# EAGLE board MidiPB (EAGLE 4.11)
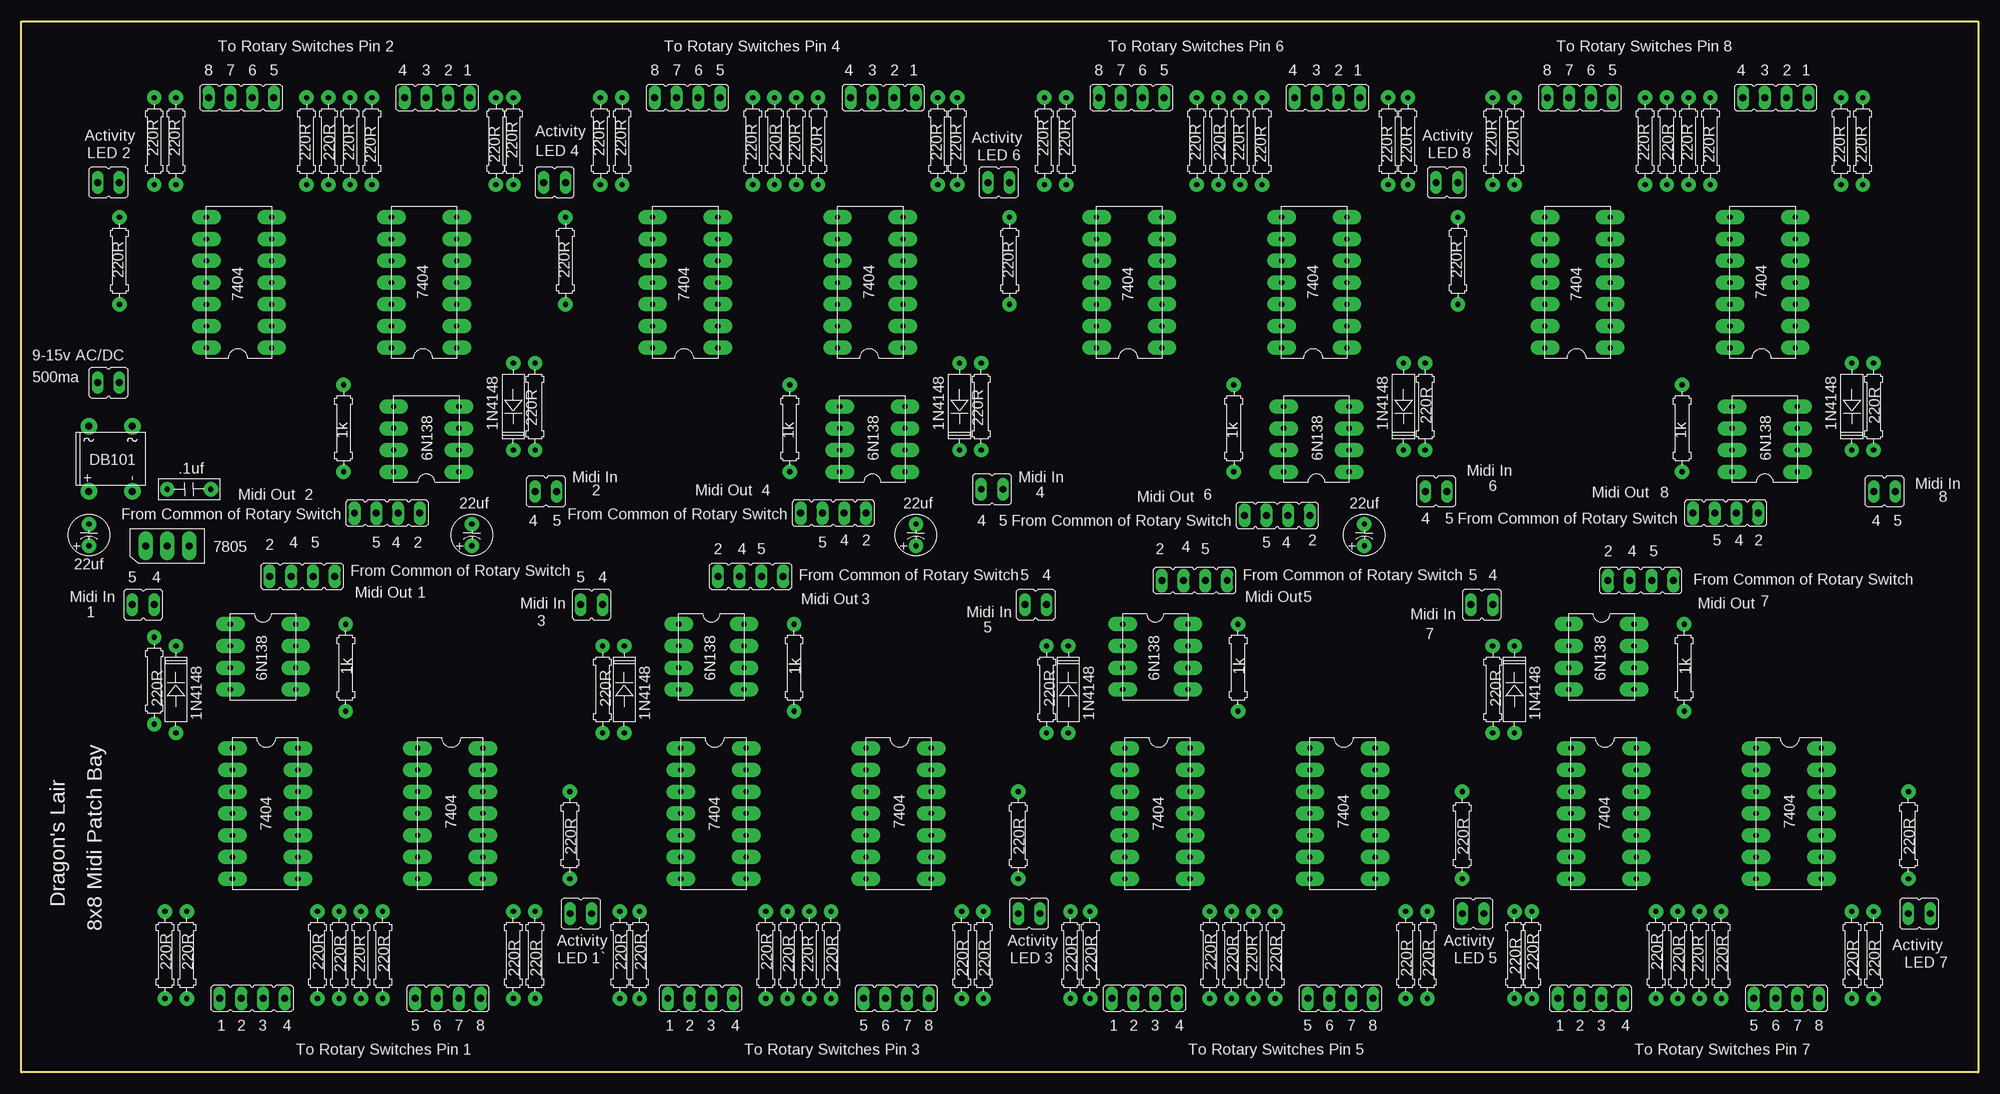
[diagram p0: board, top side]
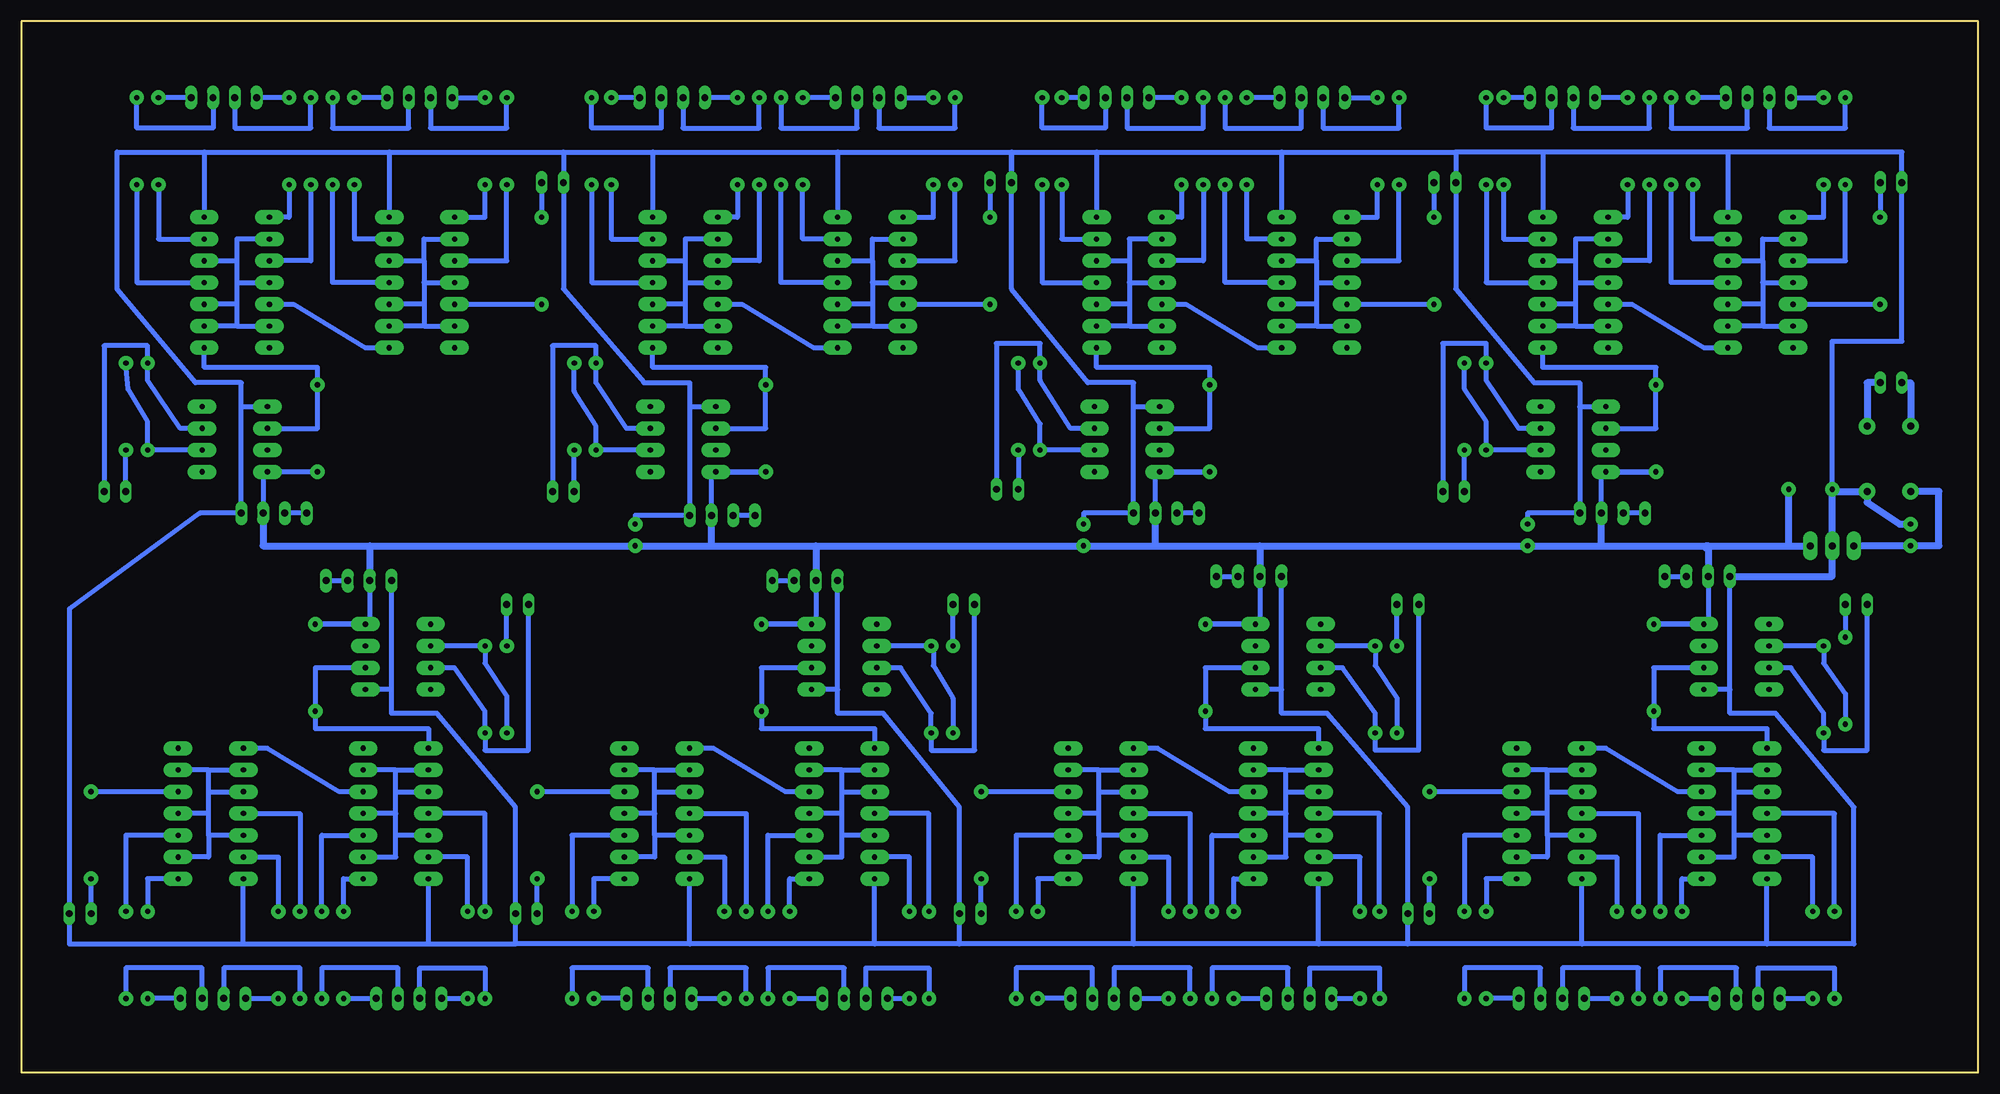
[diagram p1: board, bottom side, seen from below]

Size 228.35 x 122.68 mm. Coordinates in mm from the lower left corner, seen from the top.
Outline: 228.35,122.68 228.35,0 0,0 0,122.68 228.35,122.68
Copper layers (1*16): Top 0.035mm / dielectric 1.5mm / Bottom 0.035mm
Design rules "default": minimum track width 10mil, minimum drill 24mil, track to track 8mil, track to pad 8mil, pad to pad 8mil, via to via 8mil, smd to smd 8mil, copper to edge 40mil, drill to drill 8mil, minimum pad ring 10mil, minimum via ring 8mil, stop-mask expansion 4mil, vias tented up to drill 0mil, thermal gap 10mil

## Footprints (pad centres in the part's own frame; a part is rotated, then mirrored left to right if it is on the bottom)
DIP-8 = drill 0.61 pad 1.676 long: P$1 -3.81,3.81; P$2 -3.81,1.27; P$3 -3.81,-1.27; P$4 -3.81,-3.81; P$5 3.81,-3.81; P$6 3.81,-1.27; P$7 3.81,1.27; P$8 3.81,3.81
DIP-14 = drill 0.61 pad 1.676 long: P$1 -3.81,0; P$2 3.81,0; P$3 3.81,2.54; P$4 -3.81,2.54; P$5 -3.81,5.08; P$6 3.81,5.08; P$7 3.81,-2.54; P$8 -3.81,-2.54; P$9 -3.81,-5.08; P$10 3.81,-5.08; P$11 3.81,7.62; P$12 -3.81,7.62; P$13 -3.81,-7.62; P$14 3.81,-7.62
DIODE-1AMP = drill 0.61 pad 1.676 round: P$1 -5.08,0; P$2 5.08,0
RESISTOR = drill 0.61 pad 1.676 round: P$1 -5.08,0; P$2 5.08,0
HEADER-2 = drill 0.813 long: P$1 -1.27,0; P$2 1.27,0
HEADER-4 = drill 0.813 pad 1.422 long: P$1 -3.81,0; P$2 -1.27,0; P$3 1.27,0; P$4 3.81,0
ELECTROLYTIC1/1 = drill 0.61 pad 1.676 round: P$1 1.27,0; P$2 -1.27,0
CERAMIC1/2 = drill 0.61 pad 1.676 round: P$1 -2.54,0; P$2 2.54,0
TO-220 = drill 0.813 pad 1.676 long: P$1 -1.27,0; P$2 1.27,0; P$3 -3.81,0
DB101 = drill 0.813 pad 1.93 round: P$1 -3.81,-2.54; P$2 -3.81,2.54; P$3 3.81,2.54; P$4 3.81,-2.54

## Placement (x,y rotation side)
E$1  [DIP-8]  28.19,48.51 0 top
E$2  [DIP-14]  28.45,30.23 0 top
E$3  [DIP-14]  50.04,30.23 0 top
E$4  [DIODE-1AMP]  18.03,44.7 270 top
E$5  [RESISTOR]  37.85,47.24 90 top
E$6  [RESISTOR]  15.49,45.72 270 top
E$7  [RESISTOR]  16.76,13.72 90 top
E$8  [RESISTOR]  19.3,13.72 90 top
E$9  [RESISTOR]  34.54,13.72 90 top
E$10  [RESISTOR]  37.08,13.72 90 top
E$11  [RESISTOR]  39.62,13.72 90 top
E$12  [RESISTOR]  42.16,13.72 90 top
E$13  [RESISTOR]  59.94,13.72 90 top
E$14  [RESISTOR]  57.4,13.72 90 top
E$15  [RESISTOR]  64.01,27.69 90 top
E$16  [HEADER-2]  14.22,54.61 0 top
E$17  [HEADER-2]  65.28,18.54 0 top
E$18  [HEADER-4]  26.92,8.64 0 top
E$19  [HEADER-4]  49.78,8.64 0 top
E$20  [DIP-8]  80.52,48.51 0 top
E$21  [HEADER-4]  32.77,57.91 0 top
E$22  [DIP-14]  80.77,30.23 0 top
E$23  [DIP-14]  102.36,30.23 0 top
E$24  [DIODE-1AMP]  70.36,44.7 270 top
E$25  [RESISTOR]  90.17,47.24 90 top
E$26  [RESISTOR]  67.82,44.7 270 top
E$27  [RESISTOR]  69.85,13.72 90 top
E$28  [RESISTOR]  72.14,13.72 90 top
E$29  [RESISTOR]  86.87,13.72 90 top
E$30  [RESISTOR]  89.41,13.72 90 top
E$31  [RESISTOR]  91.95,13.72 90 top
E$32  [RESISTOR]  94.49,13.72 90 top
E$33  [RESISTOR]  112.27,13.72 90 top
E$34  [RESISTOR]  109.73,13.72 90 top
E$35  [RESISTOR]  116.33,27.69 90 top
E$36  [HEADER-2]  66.55,54.61 0 top
E$37  [HEADER-2]  117.6,18.54 0 top
E$38  [HEADER-4]  79.25,8.64 0 top
E$39  [HEADER-4]  102.11,8.64 0 top
E$40  [HEADER-4]  85.09,57.91 0 top
E$41  [DIP-8]  132.33,48.51 0 top
E$42  [DIP-14]  132.59,30.23 0 top
E$43  [DIP-14]  154.18,30.23 0 top
E$44  [DIODE-1AMP]  122.17,44.7 270 top
E$45  [RESISTOR]  141.99,47.24 90 top
E$46  [RESISTOR]  119.63,44.7 270 top
E$47  [RESISTOR]  122.43,13.72 90 top
E$48  [RESISTOR]  124.71,13.72 90 top
E$49  [RESISTOR]  138.68,13.72 90 top
E$50  [RESISTOR]  141.22,13.72 90 top
E$51  [RESISTOR]  143.76,13.72 90 top
E$52  [RESISTOR]  146.3,13.72 90 top
E$53  [RESISTOR]  164.08,13.72 90 top
E$54  [RESISTOR]  161.54,13.72 90 top
E$55  [RESISTOR]  168.15,27.69 90 top
E$56  [HEADER-2]  118.36,54.61 0 top
E$57  [HEADER-2]  169.42,18.54 0 top
E$58  [HEADER-4]  131.06,8.64 0 top
E$59  [HEADER-4]  153.92,8.64 0 top
E$60  [HEADER-4]  136.91,57.4 0 top
E$61  [DIP-8]  184.4,48.51 0 top
E$62  [DIP-14]  184.66,30.23 0 top
E$63  [DIP-14]  206.25,30.23 0 top
E$64  [DIODE-1AMP]  174.24,44.7 270 top
E$65  [RESISTOR]  194.06,47.24 90 top
E$66  [RESISTOR]  171.7,44.7 270 top
E$67  [RESISTOR]  174.24,13.72 90 top
E$68  [RESISTOR]  176.28,13.72 90 top
E$69  [RESISTOR]  190.75,13.72 90 top
E$70  [RESISTOR]  193.29,13.72 90 top
E$71  [RESISTOR]  195.83,13.72 90 top
E$72  [RESISTOR]  198.37,13.72 90 top
E$73  [RESISTOR]  216.15,13.72 90 top
E$74  [RESISTOR]  213.61,13.72 90 top
E$75  [RESISTOR]  220.22,27.69 90 top
E$76  [HEADER-2]  170.43,54.61 0 top
E$77  [HEADER-2]  221.49,18.54 0 top
E$78  [HEADER-4]  183.13,8.64 0 top
E$79  [HEADER-4]  205.99,8.64 0 top
E$80  [HEADER-4]  188.98,57.4 0 top
E$81  [DIP-8]  203.45,73.91 180 top
E$82  [DIP-14]  203.2,92.2 180 top
E$83  [DIP-14]  181.61,92.2 180 top
E$84  [DIODE-1AMP]  213.61,77.72 90 top
E$85  [RESISTOR]  193.8,75.18 270 top
E$86  [RESISTOR]  216.15,77.72 90 top
E$87  [RESISTOR]  214.88,108.71 270 top
E$88  [RESISTOR]  212.34,108.71 270 top
E$89  [RESISTOR]  197.1,108.71 270 top
E$90  [RESISTOR]  194.56,108.71 270 top
E$91  [RESISTOR]  192.02,108.71 270 top
E$92  [RESISTOR]  189.48,108.71 270 top
E$93  [RESISTOR]  171.7,108.71 270 top
E$94  [RESISTOR]  174.24,108.71 270 top
E$95  [RESISTOR]  167.64,94.74 270 top
E$96  [HEADER-2]  217.42,67.82 180 top
E$97  [HEADER-2]  166.37,103.89 180 top
E$98  [HEADER-4]  204.72,113.79 180 top
E$99  [HEADER-4]  181.86,113.79 180 top
E$100  [HEADER-4]  198.88,65.28 180 top
E$101  [DIP-8]  151.13,73.91 180 top
E$102  [DIP-14]  150.88,92.2 180 top
E$103  [DIP-14]  129.29,92.2 180 top
E$104  [DIODE-1AMP]  161.29,77.72 90 top
E$105  [RESISTOR]  141.48,75.18 270 top
E$106  [RESISTOR]  163.83,77.72 90 top
E$107  [RESISTOR]  161.8,108.71 270 top
E$108  [RESISTOR]  159.51,108.71 270 top
E$109  [RESISTOR]  144.78,108.71 270 top
E$110  [RESISTOR]  142.24,108.71 270 top
E$111  [RESISTOR]  139.7,108.71 270 top
E$112  [RESISTOR]  137.16,108.71 270 top
E$113  [RESISTOR]  119.38,108.71 270 top
E$114  [RESISTOR]  121.92,108.71 270 top
E$115  [RESISTOR]  115.32,94.74 270 top
E$116  [HEADER-2]  165.1,67.82 180 top
E$117  [HEADER-2]  114.05,103.89 180 top
E$118  [HEADER-4]  152.4,113.79 180 top
E$119  [HEADER-4]  129.54,113.79 180 top
E$120  [HEADER-4]  146.56,65.02 180 top
E$121  [DIP-8]  99.31,73.91 180 top
E$122  [DIP-14]  99.06,92.2 180 top
E$123  [DIP-14]  77.47,92.2 180 top
E$124  [DIODE-1AMP]  109.47,77.72 90 top
E$125  [RESISTOR]  89.66,75.18 270 top
E$126  [RESISTOR]  112.01,77.72 90 top
E$127  [RESISTOR]  109.22,108.71 270 top
E$128  [RESISTOR]  106.93,108.71 270 top
E$129  [RESISTOR]  92.96,108.71 270 top
E$130  [RESISTOR]  90.42,108.71 270 top
E$131  [RESISTOR]  87.88,108.71 270 top
E$132  [RESISTOR]  85.34,108.71 270 top
E$133  [RESISTOR]  67.56,108.71 270 top
E$134  [RESISTOR]  70.1,108.71 270 top
E$135  [RESISTOR]  63.5,94.74 270 top
E$136  [HEADER-2]  113.28,68.07 180 top
E$137  [HEADER-2]  62.23,103.89 180 top
E$138  [HEADER-4]  100.58,113.79 180 top
E$139  [HEADER-4]  77.72,113.79 180 top
E$140  [HEADER-4]  94.74,65.28 180 top
E$141  [DIP-8]  47.24,73.91 180 top
E$142  [DIP-14]  46.99,92.2 180 top
E$143  [DIP-14]  25.4,92.2 180 top
E$144  [DIODE-1AMP]  57.4,77.72 90 top
E$145  [RESISTOR]  37.59,75.18 270 top
E$146  [RESISTOR]  59.94,77.72 90 top
E$147  [RESISTOR]  57.4,108.71 270 top
E$148  [RESISTOR]  55.37,108.71 270 top
E$149  [RESISTOR]  40.89,108.71 270 top
E$150  [RESISTOR]  38.35,108.71 270 top
E$151  [RESISTOR]  35.81,108.71 270 top
E$152  [RESISTOR]  33.27,108.71 270 top
E$153  [RESISTOR]  15.49,108.71 270 top
E$154  [RESISTOR]  18.03,108.71 270 top
E$155  [RESISTOR]  11.43,94.74 270 top
E$156  [HEADER-2]  61.21,67.82 180 top
E$157  [HEADER-2]  10.16,103.89 180 top
E$158  [HEADER-4]  48.51,113.79 180 top
E$159  [HEADER-4]  25.65,113.79 180 top
E$160  [HEADER-4]  42.67,65.28 180 top
E$161  [ELECTROLYTIC1/1]  52.58,62.74 270 top
E$162  [ELECTROLYTIC1/1]  104.39,62.74 270 top
E$163  [ELECTROLYTIC1/1]  156.72,62.74 270 top
E$164  [ELECTROLYTIC1/1]  7.87,62.74 270 top
E$165  [CERAMIC1/2]  19.56,68.07 180 top
E$166  [TO-220]  15.75,61.47 180 top
E$167  [HEADER-2]  10.16,80.52 180 top
E$168  [DB101]  10.41,71.63 90 top

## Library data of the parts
E$1-E$168 = Daves

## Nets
S$1: E$1.P$2 E$4.P$1 E$6.P$2
S$2: E$1.P$3 E$4.P$2 E$16.P$1
S$3: E$1.P$8 E$5.P$2 E$20.P$8 E$21.P$2 E$25.P$2 E$40.P$2 E$41.P$8 E$45.P$2 E$60.P$2 E$61.P$8 E$65.P$2 E$80.P$2 E$81.P$8 E$85.P$2 E$100.P$2 E$101.P$8 E$105.P$2 E$120.P$2 E$121.P$8 E$125.P$2 E$140.P$2 E$141.P$8 E$145.P$2 E$160.P$2 E$165.P$1 E$166.P$3
S$4: E$1.P$6 E$2.P$12 E$5.P$1
S$5: E$2.P$2 E$2.P$4 E$2.P$5 E$2.P$6 E$2.P$8 E$2.P$10
S$6: E$2.P$9 E$8.P$2
S$7: E$2.P$1 E$7.P$2
S$8: E$2.P$14 E$9.P$2
S$9: E$2.P$7 E$10.P$2
S$10: E$2.P$3 E$3.P$12
S$11: E$3.P$2 E$3.P$4 E$3.P$5 E$3.P$6 E$3.P$8 E$3.P$10
S$12: E$3.P$9 E$12.P$2
S$13: E$3.P$1 E$11.P$2
S$14: E$3.P$14 E$14.P$2
S$15: E$3.P$7 E$13.P$2
S$16: E$3.P$3 E$15.P$2
S$17: E$15.P$1 E$17.P$1
S$18: E$6.P$1 E$16.P$2
S$19: E$26.P$1 E$36.P$2
S$20: E$8.P$1 E$18.P$1
S$21: E$7.P$1 E$18.P$2
S$22: E$9.P$1 E$18.P$4
S$23: E$10.P$1 E$18.P$3
S$24: E$12.P$1 E$19.P$1
S$25: E$14.P$1 E$19.P$4
S$26: E$11.P$1 E$19.P$2
S$27: E$13.P$1 E$19.P$3
S$28: E$21.P$3 E$21.P$4
S$29: E$20.P$2 E$24.P$1 E$26.P$2
S$30: E$20.P$3 E$24.P$2 E$36.P$1
S$31: E$164.P$1 E$166.P$2 E$168.P$2
S$32: E$20.P$6 E$22.P$12 E$25.P$1
S$33: E$22.P$2 E$22.P$4 E$22.P$5 E$22.P$6 E$22.P$8 E$22.P$10
S$34: E$22.P$9 E$28.P$2
S$35: E$22.P$1 E$27.P$2
S$36: E$22.P$14 E$29.P$2
S$37: E$22.P$7 E$30.P$2
S$38: E$22.P$3 E$23.P$12
S$39: E$23.P$2 E$23.P$4 E$23.P$5 E$23.P$6 E$23.P$8 E$23.P$10
S$40: E$23.P$9 E$32.P$2
S$41: E$23.P$1 E$31.P$2
S$42: E$23.P$14 E$34.P$2
S$43: E$23.P$7 E$33.P$2
S$44: E$23.P$3 E$35.P$2
S$45: E$35.P$1 E$37.P$1
S$46: E$41.P$2 E$44.P$1 E$46.P$2
S$47: E$46.P$1 E$56.P$2
S$48: E$28.P$1 E$38.P$1
S$49: E$27.P$1 E$38.P$2
S$50: E$29.P$1 E$38.P$4
S$51: E$30.P$1 E$38.P$3
S$52: E$32.P$1 E$39.P$1
S$53: E$34.P$1 E$39.P$4
S$54: E$31.P$1 E$39.P$2
S$55: E$33.P$1 E$39.P$3
S$56: E$40.P$3 E$40.P$4
S$57: E$41.P$3 E$44.P$2 E$56.P$1
S$58: E$1.P$5 E$2.P$13 E$3.P$13 E$17.P$2 E$20.P$5 E$21.P$1 E$22.P$13 E$23.P$13 E$37.P$2 E$40.P$1 E$141.P$5 E$142.P$13 E$143.P$13 E$157.P$2 E$160.P$1 E$161.P$2 E$164.P$2 E$165.P$2 E$166.P$1 E$168.P$1
S$59: E$41.P$6 E$42.P$12 E$45.P$1
S$60: E$42.P$2 E$42.P$4 E$42.P$5 E$42.P$6 E$42.P$8 E$42.P$10
S$61: E$42.P$9 E$48.P$2
S$62: E$42.P$1 E$47.P$2
S$63: E$42.P$14 E$49.P$2
S$64: E$42.P$7 E$50.P$2
S$65: E$42.P$3 E$43.P$12
S$66: E$43.P$2 E$43.P$4 E$43.P$5 E$43.P$6 E$43.P$8 E$43.P$10
S$67: E$43.P$9 E$52.P$2
S$68: E$43.P$1 E$51.P$2
S$69: E$43.P$14 E$54.P$2
S$70: E$43.P$7 E$53.P$2
S$71: E$43.P$3 E$55.P$2
S$72: E$55.P$1 E$57.P$1
S$73: E$41.P$5 E$42.P$13 E$43.P$13 E$57.P$2 E$60.P$1
S$74: E$66.P$1 E$76.P$2
S$75: E$48.P$1 E$58.P$1
S$76: E$47.P$1 E$58.P$2
S$77: E$49.P$1 E$58.P$4
S$78: E$50.P$1 E$58.P$3
S$79: E$52.P$1 E$59.P$1
S$80: E$54.P$1 E$59.P$4
S$81: E$51.P$1 E$59.P$2
S$82: E$53.P$1 E$59.P$3
S$83: E$60.P$3 E$60.P$4
S$84: E$61.P$2 E$64.P$1 E$66.P$2
S$85: E$61.P$3 E$64.P$2 E$76.P$1
S$86: E$167.P$2 E$168.P$3
S$87: E$61.P$6 E$62.P$12 E$65.P$1
S$88: E$62.P$2 E$62.P$4 E$62.P$5 E$62.P$6 E$62.P$8 E$62.P$10
S$89: E$62.P$9 E$68.P$2
S$90: E$62.P$1 E$67.P$2
S$91: E$62.P$14 E$69.P$2
S$92: E$62.P$7 E$70.P$2
S$93: E$62.P$3 E$63.P$12
S$94: E$63.P$2 E$63.P$4 E$63.P$5 E$63.P$6 E$63.P$8 E$63.P$10
S$95: E$63.P$9 E$72.P$2
S$96: E$63.P$1 E$71.P$2
S$97: E$63.P$14 E$74.P$2
S$98: E$63.P$7 E$73.P$2
S$99: E$63.P$3 E$75.P$2
S$100: E$75.P$1 E$77.P$1
S$101: E$167.P$1 E$168.P$4
S$102: E$86.P$1 E$96.P$2
S$103: E$68.P$1 E$78.P$1
S$104: E$67.P$1 E$78.P$2
S$105: E$69.P$1 E$78.P$4
S$106: E$70.P$1 E$78.P$3
S$107: E$72.P$1 E$79.P$1
S$108: E$74.P$1 E$79.P$4
S$109: E$71.P$1 E$79.P$2
S$110: E$73.P$1 E$79.P$3
S$111: E$80.P$3 E$80.P$4
S$112: E$81.P$2 E$84.P$1 E$86.P$2
S$113: E$81.P$3 E$84.P$2 E$96.P$1
S$114: E$106.P$1 E$116.P$2
S$115: E$81.P$6 E$82.P$12 E$85.P$1
S$116: E$82.P$2 E$82.P$4 E$82.P$5 E$82.P$6 E$82.P$8 E$82.P$10
S$117: E$82.P$9 E$88.P$2
S$118: E$82.P$1 E$87.P$2
S$119: E$82.P$14 E$89.P$2
S$120: E$82.P$7 E$90.P$2
S$121: E$82.P$3 E$83.P$12
S$122: E$83.P$2 E$83.P$4 E$83.P$5 E$83.P$6 E$83.P$8 E$83.P$10
S$123: E$83.P$9 E$92.P$2
S$124: E$83.P$1 E$91.P$2
S$125: E$83.P$14 E$94.P$2
S$126: E$83.P$7 E$93.P$2
S$127: E$83.P$3 E$95.P$2
S$128: E$95.P$1 E$97.P$1
S$129: E$61.P$5 E$62.P$13 E$63.P$13 E$77.P$2 E$80.P$1 E$81.P$5 E$82.P$13 E$83.P$13 E$97.P$2 E$100.P$1 E$101.P$5 E$102.P$13 E$103.P$13 E$117.P$2 E$120.P$1 E$163.P$2
S$130: E$146.P$1 E$156.P$2
S$131: E$88.P$1 E$98.P$1
S$132: E$87.P$1 E$98.P$2
S$133: E$89.P$1 E$98.P$4
S$134: E$90.P$1 E$98.P$3
S$135: E$92.P$1 E$99.P$1
S$136: E$94.P$1 E$99.P$4
S$137: E$91.P$1 E$99.P$2
S$138: E$93.P$1 E$99.P$3
S$139: E$100.P$3 E$100.P$4
S$140: E$101.P$2 E$104.P$1 E$106.P$2
S$141: E$101.P$3 E$104.P$2 E$116.P$1
S$142: E$126.P$1 E$136.P$2
S$143: E$101.P$6 E$102.P$12 E$105.P$1
S$144: E$102.P$2 E$102.P$4 E$102.P$5 E$102.P$6 E$102.P$8 E$102.P$10
S$145: E$102.P$9 E$108.P$2
S$146: E$102.P$1 E$107.P$2
S$147: E$102.P$14 E$109.P$2
S$148: E$102.P$7 E$110.P$2
S$149: E$102.P$3 E$103.P$12
S$150: E$103.P$2 E$103.P$4 E$103.P$5 E$103.P$6 E$103.P$8 E$103.P$10
S$151: E$103.P$9 E$112.P$2
S$152: E$103.P$1 E$111.P$2
S$153: E$103.P$14 E$114.P$2
S$154: E$103.P$7 E$113.P$2
S$155: E$103.P$3 E$115.P$2
S$156: E$115.P$1 E$117.P$1
S$158: E$108.P$1 E$118.P$1
S$159: E$107.P$1 E$118.P$2
S$160: E$109.P$1 E$118.P$4
S$161: E$110.P$1 E$118.P$3
S$162: E$112.P$1 E$119.P$1
S$163: E$114.P$1 E$119.P$4
S$164: E$111.P$1 E$119.P$2
S$165: E$113.P$1 E$119.P$3
S$166: E$120.P$3 E$120.P$4
S$167: E$121.P$2 E$124.P$1 E$126.P$2
S$168: E$121.P$3 E$124.P$2 E$136.P$1
S$170: E$121.P$6 E$122.P$12 E$125.P$1
S$171: E$122.P$2 E$122.P$4 E$122.P$5 E$122.P$6 E$122.P$8 E$122.P$10
S$172: E$122.P$9 E$128.P$2
S$173: E$122.P$1 E$127.P$2
S$174: E$122.P$14 E$129.P$2
S$175: E$122.P$7 E$130.P$2
S$176: E$122.P$3 E$123.P$12
S$177: E$123.P$2 E$123.P$4 E$123.P$5 E$123.P$6 E$123.P$8 E$123.P$10
S$178: E$123.P$9 E$132.P$2
S$179: E$123.P$1 E$131.P$2
S$180: E$123.P$14 E$134.P$2
S$181: E$123.P$7 E$133.P$2
S$182: E$123.P$3 E$135.P$2
S$183: E$135.P$1 E$137.P$1
S$184: E$121.P$5 E$122.P$13 E$123.P$13 E$137.P$2 E$140.P$1 E$162.P$2
S$186: E$128.P$1 E$138.P$1
S$187: E$127.P$1 E$138.P$2
S$188: E$129.P$1 E$138.P$4
S$189: E$130.P$1 E$138.P$3
S$190: E$132.P$1 E$139.P$1
S$191: E$134.P$1 E$139.P$4
S$192: E$131.P$1 E$139.P$2
S$193: E$133.P$1 E$139.P$3
S$194: E$140.P$3 E$140.P$4
S$195: E$141.P$2 E$144.P$1 E$146.P$2
S$196: E$141.P$3 E$144.P$2 E$156.P$1
S$198: E$141.P$6 E$142.P$12 E$145.P$1
S$199: E$142.P$2 E$142.P$4 E$142.P$5 E$142.P$6 E$142.P$8 E$142.P$10
S$200: E$142.P$9 E$148.P$2
S$201: E$142.P$1 E$147.P$2
S$202: E$142.P$14 E$149.P$2
S$203: E$142.P$7 E$150.P$2
S$204: E$142.P$3 E$143.P$12
S$205: E$143.P$2 E$143.P$4 E$143.P$5 E$143.P$6 E$143.P$8 E$143.P$10
S$206: E$143.P$9 E$152.P$2
S$207: E$143.P$1 E$151.P$2
S$208: E$143.P$14 E$154.P$2
S$209: E$143.P$7 E$153.P$2
S$210: E$143.P$3 E$155.P$2
S$211: E$155.P$1 E$157.P$1
S$214: E$148.P$1 E$158.P$1
S$215: E$147.P$1 E$158.P$2
S$216: E$149.P$1 E$158.P$4
S$217: E$150.P$1 E$158.P$3
S$218: E$152.P$1 E$159.P$1
S$219: E$154.P$1 E$159.P$4
S$220: E$151.P$1 E$159.P$2
S$221: E$153.P$1 E$159.P$3
S$222: E$160.P$3 E$160.P$4

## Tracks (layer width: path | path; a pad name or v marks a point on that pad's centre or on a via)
S$1
  Bottom 0.61: E$1.P$2 E$4.P$1 18.03,47.75 15.49,44.2 E$6.P$2
S$2
  Bottom 0.61: E$1.P$3 21.84,47.24 18.03,41.91 E$4.P$2 18.03,37.59 12.95,37.59 E$16.P$1
S$3
  Bottom 0.61: E$1.P$8 E$5.P$2 31.5,52.32 E$21.P$2 | E$141.P$8 E$145.P$2 43.94,70.1 E$160.P$2 | E$20.P$8 E$25.P$2 83.82,52.32 E$40.P$2 | E$121.P$8 E$125.P$2 96.01,70.1 E$140.P$2 96.01,65.02 | E$41.P$8 E$45.P$2 135.64,52.32 E$60.P$2 | E$101.P$8 E$105.P$2 147.83,70.1 E$120.P$2 | E$61.P$8 E$65.P$2 187.71,52.32 E$80.P$2 | E$81.P$8 E$85.P$2 200.15,70.1 E$100.P$2
  Bottom 0.813: E$21.P$2 31.5,61.47 31.75,61.47 | 43.94,61.47 31.75,61.47 | 43.94,61.47 E$160.P$2 | 83.82,61.47 43.94,61.47 | 83.82,61.47 E$40.P$2 | 96.01,61.47 83.82,61.47 | 96.01,61.47 96.01,65.02 | 96.01,61.47 E$140.P$2 | 135.64,61.47 96.01,61.47 | 135.64,61.47 E$60.P$2 | 147.83,61.47 135.64,61.47 | 147.83,61.47 E$120.P$2 | 187.71,61.47 147.83,61.47 | 187.71,61.47 E$80.P$2 | 187.71,61.47 200.15,61.47 E$100.P$2 | 22.1,61.47 E$165.P$1 | 31.75,61.47 31.75,61.21 | 31.75,61.47 22.1,61.47 | 22.1,61.47 E$166.P$3
S$4
  Bottom 0.61: E$1.P$6 37.85,47.24 E$5.P$1 37.85,40.13 24.64,40.13 E$2.P$12
S$5
  Bottom 0.61: 32.51,35.31 E$2.P$6 28.45,35.31 | 28.45,35.31 E$2.P$5 | 28.45,32.77 E$2.P$4 | 28.45,32.77 28.45,35.31 | 28.45,30.23 E$2.P$2 | 28.45,30.23 28.45,32.77 | E$2.P$8 28.45,27.69 | 28.45,27.69 28.45,30.23 | E$2.P$10 28.45,25.15 28.45,27.69
S$6
  Bottom 0.61: E$8.P$2 19.3,25.15 E$2.P$9
S$7
  Bottom 0.61: E$7.P$2 16.76,30.23 E$2.P$1
S$8
  Bottom 0.61: E$9.P$2 34.54,22.61 E$2.P$14
S$9
  Bottom 0.61: E$10.P$2 37.08,27.69 E$2.P$7
S$10
  Bottom 0.61: E$2.P$3 35.05,32.77 43.43,37.85 E$3.P$12
S$11
  Bottom 0.61: E$3.P$10 50.29,25.15 50.29,27.69 | E$3.P$8 50.29,27.69 | 50.29,30.23 E$3.P$2 | 50.29,27.69 50.29,30.23 | 50.29,32.77 E$3.P$4 | 50.29,30.23 50.29,32.77 | 50.29,35.31 E$3.P$6 | 50.29,32.77 50.29,35.31 | 50.29,35.31 E$3.P$5
S$12
  Bottom 0.61: E$3.P$9 42.16,25.15 E$12.P$2
S$13
  Bottom 0.61: E$3.P$1 39.62,30.23 E$11.P$2
S$14
  Bottom 0.61: E$3.P$14 57.4,22.61 E$14.P$2
S$15
  Bottom 0.61: E$3.P$7 59.94,27.69 E$13.P$2
S$16
  Bottom 0.61: E$3.P$3 E$15.P$2
S$17
  Bottom 0.61: E$17.P$1 E$15.P$1
S$18
  Bottom 0.61: E$16.P$2 E$6.P$1
S$19
  Bottom 0.61: E$26.P$1 E$36.P$2
S$20
  Bottom 0.61: E$18.P$1 E$8.P$1
S$21
  Bottom 0.61: E$18.P$2 25.65,12.19 16.76,12.19 E$7.P$1
S$22
  Bottom 0.61: E$9.P$1 E$18.P$4
S$23
  Bottom 0.61: E$18.P$3 28.19,12.19 37.08,12.19 E$10.P$1
S$24
  Bottom 0.61: E$19.P$1 E$12.P$1
S$25
  Bottom 0.61: E$19.P$4 E$14.P$1
S$26
  Bottom 0.61: E$11.P$1 39.62,12.19 48.51,12.19 E$19.P$2
S$27
  Bottom 0.61: E$19.P$3 51.05,12.19 59.94,12.19 E$13.P$1
S$28
  Bottom 0.61: E$21.P$4 E$21.P$3
S$29
  Bottom 0.61: E$20.P$2 E$24.P$1 70.36,47.5 67.82,43.69 E$26.P$2
S$30
  Bottom 0.61: E$20.P$3 74.17,47.24 70.36,41.91 70.36,39.88 | 70.36,39.88 E$24.P$2 | E$36.P$1 65.28,37.59 70.36,37.59 70.36,39.88
S$31
  Bottom 0.813: E$168.P$2 4.57,67.82 4.57,61.47 E$164.P$1 | E$164.P$1 8.13,61.47 | E$164.P$1 E$166.P$2
S$32
  Bottom 0.61: E$20.P$6 90.17,47.24 E$25.P$1 90.17,40.13 76.96,40.13 E$22.P$12
S$33
  Bottom 0.61: 84.84,35.31 E$22.P$6 80.77,35.31 | 80.77,35.31 E$22.P$5 | 80.77,32.77 E$22.P$4 | 80.77,32.77 80.77,35.31 | 80.77,30.23 E$22.P$2 | 80.77,30.23 80.77,32.77 | E$22.P$8 80.77,27.69 | 80.77,27.69 80.77,30.23 | E$22.P$10 80.77,25.15 80.77,27.69
S$34
  Bottom 0.61: E$28.P$2 72.14,25.15 E$22.P$9
S$35
  Bottom 0.61: E$27.P$2 69.85,30.23 E$22.P$1
S$36
  Bottom 0.61: E$29.P$2 86.87,22.61 E$22.P$14
S$37
  Bottom 0.61: E$30.P$2 89.41,27.69 E$22.P$7
S$38
  Bottom 0.61: E$22.P$3 87.38,32.77 95.76,37.85 E$23.P$12
S$39
  Bottom 0.61: E$23.P$10 102.62,25.15 102.62,27.69 | E$23.P$8 102.62,27.69 | 102.62,30.23 E$23.P$2 | 102.62,27.69 102.62,30.23 | 102.62,32.77 E$23.P$4 | 102.62,30.23 102.62,32.77 | 102.62,35.31 E$23.P$6 | 102.62,32.77 102.62,35.31 | 102.62,35.31 E$23.P$5
S$40
  Bottom 0.61: E$23.P$9 94.49,25.15 E$32.P$2
S$41
  Bottom 0.61: E$23.P$1 91.95,30.23 E$31.P$2
S$42
  Bottom 0.61: E$23.P$14 109.73,22.61 E$34.P$2
S$43
  Bottom 0.61: E$23.P$7 112.27,27.69 E$33.P$2
S$44
  Bottom 0.61: E$23.P$3 E$35.P$2
S$45
  Bottom 0.61: E$37.P$1 E$35.P$1
S$46
  Bottom 0.61: E$41.P$2 E$44.P$1 121.92,49.78 121.92,47.5 119.63,43.69 E$46.P$2
S$47
  Bottom 0.61: 119.63,54.86 E$56.P$2 E$46.P$1
S$48
  Bottom 0.61: E$38.P$1 E$28.P$1
S$49
  Bottom 0.61: E$38.P$2 77.98,12.19 69.85,12.19 E$27.P$1
S$50
  Bottom 0.61: E$29.P$1 E$38.P$4
S$51
  Bottom 0.61: E$38.P$3 80.52,12.19 89.41,12.19 E$30.P$1
S$52
  Bottom 0.61: E$39.P$1 E$32.P$1
S$53
  Bottom 0.61: E$39.P$4 E$34.P$1
S$54
  Bottom 0.61: E$31.P$1 91.95,12.19 100.84,12.19 E$39.P$2
S$55
  Bottom 0.61: E$39.P$3 103.38,12.19 112.27,12.19 E$33.P$1
S$56
  Bottom 0.61: E$40.P$4 E$40.P$3
S$57
  Bottom 0.61: E$41.P$3 125.73,47.24 122.17,41.91 E$44.P$2 122.17,37.59 117.09,37.59 E$56.P$1
S$58
  Bottom 0.61: 32.26,44.7 E$1.P$5 28.96,44.7 | 28.96,44.7 28.96,41.91 23.62,41.91 14.48,30.99 14.48,14.99 24.64,14.99 | 24.64,14.99 E$2.P$13 | 24.64,14.99 46.23,14.99 | 46.23,14.99 E$3.P$13 | 46.23,14.99 66.55,14.99 | 28.96,44.7 E$21.P$1 | 84.58,44.7 E$20.P$5 81.28,44.7 | 81.28,44.7 81.28,41.91 75.95,41.91 66.55,30.99 E$17.P$2 66.55,14.99 | 66.55,14.99 76.96,14.99 | 76.96,14.99 E$22.P$13 | 76.96,14.99 98.55,14.99 | E$37.P$2 118.87,14.99 98.55,14.99 | 98.55,14.99 E$23.P$13 | 81.28,44.7 E$40.P$1 | 43.18,77.72 E$141.P$5 46.48,77.72 | 46.48,77.72 46.48,80.52 51.82,80.52 60.96,91.44 60.96,107.44 50.8,107.44 | 50.8,107.44 E$142.P$13 | 29.21,107.44 50.8,107.44 | 29.21,107.44 E$143.P$13 | 29.21,107.44 8.89,107.44 E$157.P$2 8.89,85.34 17.02,85.34 E$166.P$1 | 46.48,77.72 E$160.P$1 52.58,65.28 E$161.P$2
  Bottom 0.813: 17.02,67.82 E$166.P$1 17.02,57.91 E$21.P$1 | 17.02,67.82 E$168.P$1 12.95,66.55 9.14,64.01 E$164.P$2 7.87,64.26 | 17.02,67.82 E$165.P$2
S$59
  Bottom 0.61: E$41.P$6 141.99,47.24 E$45.P$1 141.99,40.13 128.78,40.13 E$42.P$12
S$60
  Bottom 0.61: 136.65,35.31 E$42.P$6 132.59,35.31 | 132.59,35.31 E$42.P$5 | 132.59,32.77 E$42.P$4 | 132.59,32.77 132.59,35.31 | 132.59,30.23 E$42.P$2 | 132.59,30.23 132.59,32.77 | E$42.P$8 132.59,27.69 | 132.59,27.69 132.59,30.23 | E$42.P$10 132.59,25.15 132.59,27.69
S$61
  Bottom 0.61: E$48.P$2 124.71,25.15 E$42.P$9
S$62
  Bottom 0.61: E$47.P$2 122.43,30.23 E$42.P$1
S$63
  Bottom 0.61: E$49.P$2 138.68,22.61 E$42.P$14
S$64
  Bottom 0.61: E$50.P$2 141.22,27.69 E$42.P$7
S$65
  Bottom 0.61: E$42.P$3 139.19,32.77 147.57,37.85 E$43.P$12
S$66
  Bottom 0.61: E$43.P$10 154.43,25.15 154.43,27.69 | E$43.P$8 154.43,27.69 | 154.43,30.23 E$43.P$2 | 154.43,27.69 154.43,30.23 | 154.43,32.77 E$43.P$4 | 154.43,30.23 154.43,32.77 | 154.43,35.31 E$43.P$6 | 154.43,32.77 154.43,35.31 | 154.43,35.31 E$43.P$5
S$67
  Bottom 0.61: E$43.P$9 146.3,25.15 E$52.P$2
S$68
  Bottom 0.61: E$43.P$1 143.76,30.23 E$51.P$2
S$69
  Bottom 0.61: E$43.P$14 161.54,22.61 E$54.P$2
S$70
  Bottom 0.61: E$43.P$7 164.08,27.69 E$53.P$2
S$71
  Bottom 0.61: E$43.P$3 E$55.P$2
S$72
  Bottom 0.61: E$57.P$1 E$55.P$1
S$73
  Bottom 0.61: 136.4,44.7 E$41.P$5 133.1,44.7 | 133.1,44.7 133.1,41.91 127.76,41.91 118.87,30.99 118.87,14.99 128.78,14.99 | 128.78,14.99 E$42.P$13 | 128.78,14.99 150.37,14.99 | E$57.P$2 170.69,14.99 150.37,14.99 | 150.37,14.99 E$43.P$13 | 133.1,44.7 E$60.P$1
S$74
  Bottom 0.61: 171.7,54.86 E$76.P$2 E$66.P$1
S$75
  Bottom 0.61: E$58.P$1 E$48.P$1
S$76
  Bottom 0.61: E$58.P$2 129.79,12.19 122.43,12.19 E$47.P$1
S$77
  Bottom 0.61: E$49.P$1 E$58.P$4
S$78
  Bottom 0.61: E$58.P$3 132.33,12.19 141.22,12.19 E$50.P$1
S$79
  Bottom 0.61: E$59.P$1 E$52.P$1
S$80
  Bottom 0.61: E$59.P$4 E$54.P$1
S$81
  Bottom 0.61: E$51.P$1 143.76,12.19 152.65,12.19 E$59.P$2
S$82
  Bottom 0.61: E$59.P$3 155.19,12.19 164.08,12.19 E$53.P$1
S$83
  Bottom 0.61: E$60.P$4 E$60.P$3
S$84
  Bottom 0.61: E$61.P$2 E$64.P$1 174.24,47.75 171.7,43.94 E$66.P$2
S$85
  Bottom 0.61: E$61.P$3 177.8,47.24 174.24,42.16 E$64.P$2 174.24,37.59 169.16,37.59 E$76.P$1
S$86
  Bottom 0.813: E$167.P$2 7.87,80.52 E$168.P$3
S$87
  Bottom 0.61: E$61.P$6 194.06,47.24 E$65.P$1 194.06,40.13 180.85,40.13 E$62.P$12
S$88
  Bottom 0.61: 188.72,35.31 E$62.P$6 184.66,35.31 | 184.66,35.31 E$62.P$5 | 184.66,32.77 E$62.P$4 | 184.66,32.77 184.66,35.31 | 184.66,30.23 E$62.P$2 | 184.66,30.23 184.66,32.77 | E$62.P$8 184.66,27.69 | 184.66,27.69 184.66,30.23 | E$62.P$10 184.66,25.15 184.66,27.69
S$89
  Bottom 0.61: E$68.P$2 176.28,25.15 E$62.P$9
S$90
  Bottom 0.61: E$67.P$2 174.24,30.23 E$62.P$1
S$91
  Bottom 0.61: E$69.P$2 190.75,22.61 E$62.P$14
S$92
  Bottom 0.61: E$70.P$2 193.29,27.69 E$62.P$7
S$93
  Bottom 0.61: E$62.P$3 191.26,32.77 199.64,37.85 E$63.P$12
S$94
  Bottom 0.61: E$63.P$10 206.5,25.15 206.5,27.69 | E$63.P$8 206.5,27.69 | 206.5,30.23 E$63.P$2 | 206.5,27.69 206.5,30.23 | 206.5,32.77 E$63.P$4 | 206.5,30.23 206.5,32.77 | 206.5,35.31 E$63.P$6 | 206.5,32.77 206.5,35.31 | 206.5,35.31 E$63.P$5
S$95
  Bottom 0.61: E$63.P$9 198.37,25.15 E$72.P$2
S$96
  Bottom 0.61: E$63.P$1 195.83,30.23 E$71.P$2
S$97
  Bottom 0.61: E$63.P$14 213.61,22.61 E$74.P$2
S$98
  Bottom 0.61: E$63.P$7 216.15,27.69 E$73.P$2
S$99
  Bottom 0.61: E$63.P$3 E$75.P$2
S$100
  Bottom 0.61: E$77.P$1 E$75.P$1
S$101
  Bottom 0.813: E$167.P$1 12.95,80.52 E$168.P$4
S$102
  Bottom 0.61: E$96.P$2 E$86.P$1
S$103
  Bottom 0.61: E$78.P$1 E$68.P$1
S$104
  Bottom 0.61: E$78.P$2 181.86,12.19 174.24,12.19 E$67.P$1
S$105
  Bottom 0.61: E$69.P$1 E$78.P$4
S$106
  Bottom 0.61: E$78.P$3 184.4,12.19 193.29,12.19 E$70.P$1
S$107
  Bottom 0.61: E$79.P$1 E$72.P$1
S$108
  Bottom 0.61: E$79.P$4 E$74.P$1
S$109
  Bottom 0.61: E$71.P$1 195.83,12.19 204.72,12.19 E$79.P$2
S$110
  Bottom 0.61: E$79.P$3 207.26,12.19 216.15,12.19 E$73.P$1
S$111
  Bottom 0.61: E$80.P$4 E$80.P$3
S$112
  Bottom 0.61: E$81.P$2 E$84.P$1 213.61,75.95 215.9,79.76 E$86.P$2
S$113
  Bottom 0.61: E$81.P$3 209.8,75.18 213.61,80.77 E$84.P$2 213.61,84.84 218.69,84.84 E$96.P$1
S$114
  Bottom 0.61: 163.83,72.9 E$106.P$1 E$116.P$2
S$115
  Bottom 0.61: E$81.P$6 193.8,75.18 E$85.P$1 193.8,82.3 207.01,82.3 E$82.P$12
S$116
  Bottom 0.61: 199.14,87.12 E$82.P$6 203.2,87.12 | 203.2,87.12 E$82.P$5 | 203.2,89.66 E$82.P$4 | 203.2,89.66 203.2,87.12 | 203.2,92.2 E$82.P$2 | 203.2,92.2 203.2,89.66 | E$82.P$8 203.2,94.74 | 203.2,94.74 203.2,92.2 | E$82.P$10 203.2,97.28 203.2,94.74
S$117
  Bottom 0.61: E$88.P$2 212.34,97.28 E$82.P$9
S$118
  Bottom 0.61: E$87.P$2 214.88,92.2 E$82.P$1
S$119
  Bottom 0.61: E$89.P$2 197.1,99.82 E$82.P$14
S$120
  Bottom 0.61: E$90.P$2 194.56,94.74 E$82.P$7
S$121
  Bottom 0.61: E$82.P$3 196.6,89.66 188.21,84.58 E$83.P$12
S$122
  Bottom 0.61: E$83.P$10 181.36,97.28 181.36,94.74 | E$83.P$8 181.36,94.74 | 181.36,92.2 E$83.P$2 | 181.36,94.74 181.36,92.2 | 181.36,89.66 E$83.P$4 | 181.36,92.2 181.36,89.66 | 181.36,87.12 E$83.P$6 | 181.36,89.66 181.36,87.12 | 181.36,87.12 E$83.P$5
S$123
  Bottom 0.61: E$83.P$9 189.48,97.28 E$92.P$2
S$124
  Bottom 0.61: E$83.P$1 192.02,92.2 E$91.P$2
S$125
  Bottom 0.61: E$83.P$14 174.24,99.82 E$94.P$2
S$126
  Bottom 0.61: E$83.P$7 171.7,94.74 E$93.P$2
S$127
  Bottom 0.61: E$83.P$3 E$95.P$2
S$128
  Bottom 0.61: E$97.P$1 E$95.P$1
S$129
  Bottom 0.61: 199.39,77.72 E$81.P$5 202.69,77.72 | 202.69,77.72 202.69,80.52 208.03,80.52 217.17,91.44 217.17,107.44 207.01,107.44 | 207.01,107.44 E$82.P$13 | 207.01,107.44 185.42,107.44 | 185.42,107.44 E$83.P$13 | 185.42,107.44 165.1,107.44 | 202.69,77.72 E$100.P$1 207.52,65.28 222.76,54.1 E$77.P$2 222.76,14.99 202.44,14.99 | 147.07,77.72 E$101.P$5 150.37,77.72 | 150.37,77.72 150.37,80.52 155.7,80.52 165.1,91.44 E$97.P$2 165.1,107.44 | 165.1,107.44 154.69,107.44 | 154.69,107.44 E$102.P$13 | 154.69,107.44 133.1,107.44 | E$117.P$2 112.78,107.44 133.1,107.44 | 133.1,107.44 E$103.P$13 | 150.37,77.72 E$120.P$1 156.72,65.02 E$163.P$2 | 188.47,44.7 E$61.P$5 185.17,44.7 | 185.17,44.7 185.17,41.91 179.83,41.91 170.69,30.99 170.69,14.99 180.85,14.99 | 180.85,14.99 E$62.P$13 | 202.44,14.99 180.85,14.99 | 202.44,14.99 E$63.P$13 | 185.17,44.7 E$80.P$1
S$130
  Bottom 0.61: E$156.P$2 E$146.P$1
S$131
  Bottom 0.61: E$98.P$1 E$88.P$1
S$132
  Bottom 0.61: E$98.P$2 205.99,110.24 214.88,110.24 E$87.P$1
S$133
  Bottom 0.61: E$89.P$1 E$98.P$4
S$134
  Bottom 0.61: E$98.P$3 203.45,110.24 194.56,110.24 E$90.P$1
S$135
  Bottom 0.61: E$99.P$1 E$92.P$1
S$136
  Bottom 0.61: E$99.P$4 E$94.P$1
S$137
  Bottom 0.61: E$91.P$1 192.02,110.24 183.13,110.24 E$99.P$2
S$138
  Bottom 0.61: E$99.P$3 180.59,110.24 171.7,110.24 E$93.P$1
S$139
  Bottom 0.61: E$100.P$4 E$100.P$3
S$140
  Bottom 0.61: E$101.P$2 E$104.P$1 161.29,75.44 163.83,79.5 E$106.P$2
S$141
  Bottom 0.61: E$101.P$3 157.73,75.18 161.29,80.52 E$104.P$2 161.29,84.84 166.37,84.84 E$116.P$1
S$142
  Bottom 0.61: E$126.P$1 E$136.P$2
S$143
  Bottom 0.61: E$101.P$6 141.48,75.18 E$105.P$1 141.48,82.3 154.69,82.3 E$102.P$12
S$144
  Bottom 0.61: 146.81,87.12 E$102.P$6 150.88,87.12 | 150.88,87.12 E$102.P$5 | 150.88,89.66 E$102.P$4 | 150.88,89.66 150.88,87.12 | 150.88,92.2 E$102.P$2 | 150.88,92.2 150.88,89.66 | E$102.P$8 150.88,94.74 | 150.88,94.74 150.88,92.2 | E$102.P$10 150.88,97.28 150.88,94.74
S$145
  Bottom 0.61: E$108.P$2 159.51,97.28 E$102.P$9
S$146
  Bottom 0.61: E$107.P$2 161.8,92.2 E$102.P$1
S$147
  Bottom 0.61: E$109.P$2 144.78,99.82 E$102.P$14
S$148
  Bottom 0.61: E$110.P$2 142.24,94.74 E$102.P$7
S$149
  Bottom 0.61: E$102.P$3 144.27,89.66 135.89,84.58 E$103.P$12
S$150
  Bottom 0.61: E$103.P$10 129.03,97.28 129.03,94.74 | E$103.P$8 129.03,94.74 | 129.03,92.2 E$103.P$2 | 129.03,94.74 129.03,92.2 | 129.03,89.66 E$103.P$4 | 129.03,92.2 129.03,89.66 | 129.03,87.12 E$103.P$6 | 129.03,89.66 129.03,87.12 | 129.03,87.12 E$103.P$5
S$151
  Bottom 0.61: E$103.P$9 137.16,97.28 E$112.P$2
S$152
  Bottom 0.61: E$103.P$1 139.7,92.2 E$111.P$2
S$153
  Bottom 0.61: E$103.P$14 121.92,99.82 E$114.P$2
S$154
  Bottom 0.61: E$103.P$7 119.38,94.74 E$113.P$2
S$155
  Bottom 0.61: E$103.P$3 E$115.P$2
S$156
  Bottom 0.61: E$117.P$1 E$115.P$1
S$158
  Bottom 0.61: E$118.P$1 E$108.P$1
S$159
  Bottom 0.61: E$118.P$2 153.67,110.24 161.8,110.24 E$107.P$1
S$160
  Bottom 0.61: E$109.P$1 E$118.P$4
S$161
  Bottom 0.61: E$118.P$3 151.13,110.24 142.24,110.24 E$110.P$1
S$162
  Bottom 0.61: E$119.P$1 E$112.P$1
S$163
  Bottom 0.61: E$119.P$4 E$114.P$1
S$164
  Bottom 0.61: E$111.P$1 139.7,110.24 130.81,110.24 E$119.P$2
S$165
  Bottom 0.61: E$119.P$3 128.27,110.24 119.38,110.24 E$113.P$1
S$166
  Bottom 0.61: E$120.P$4 E$120.P$3
S$167
  Bottom 0.61: E$121.P$2 E$124.P$1 109.47,75.69 112.01,79.76 E$126.P$2
S$168
  Bottom 0.61: E$121.P$3 105.92,75.18 109.47,80.77 E$124.P$2 109.47,85.09 114.55,85.09 E$136.P$1
S$170
  Bottom 0.61: E$121.P$6 89.66,75.18 E$125.P$1 89.66,82.3 102.87,82.3 E$122.P$12
S$171
  Bottom 0.61: 95,87.12 E$122.P$6 99.06,87.12 | 99.06,87.12 E$122.P$5 | 99.06,89.66 E$122.P$4 | 99.06,89.66 99.06,87.12 | 99.06,92.2 E$122.P$2 | 99.06,92.2 99.06,89.66 | E$122.P$8 99.06,94.74 | 99.06,94.74 99.06,92.2 | E$122.P$10 99.06,97.28 99.06,94.74
S$172
  Bottom 0.61: E$128.P$2 106.93,97.28 E$122.P$9
S$173
  Bottom 0.61: E$127.P$2 109.22,92.2 E$122.P$1
S$174
  Bottom 0.61: E$129.P$2 92.96,99.82 E$122.P$14
S$175
  Bottom 0.61: E$130.P$2 90.42,94.74 E$122.P$7
S$176
  Bottom 0.61: E$122.P$3 92.46,89.66 84.07,84.58 E$123.P$12
S$177
  Bottom 0.61: E$123.P$10 77.22,97.28 77.22,94.74 | E$123.P$8 77.22,94.74 | 77.22,92.2 E$123.P$2 | 77.22,94.74 77.22,92.2 | 77.22,89.66 E$123.P$4 | 77.22,92.2 77.22,89.66 | 77.22,87.12 E$123.P$6 | 77.22,89.66 77.22,87.12 | 77.22,87.12 E$123.P$5
S$178
  Bottom 0.61: E$123.P$9 85.34,97.28 E$132.P$2
S$179
  Bottom 0.61: E$123.P$1 87.88,92.2 E$131.P$2
S$180
  Bottom 0.61: E$123.P$14 70.1,99.82 E$134.P$2
S$181
  Bottom 0.61: E$123.P$7 67.56,94.74 E$133.P$2
S$182
  Bottom 0.61: E$123.P$3 E$135.P$2
S$183
  Bottom 0.61: E$137.P$1 E$135.P$1
S$184
  Bottom 0.61: 95.25,77.72 E$121.P$5 98.55,77.72 | 98.55,77.72 98.55,80.52 103.89,80.52 112.78,91.44 112.78,107.44 102.87,107.44 | 102.87,107.44 E$122.P$13 | 102.87,107.44 81.28,107.44 | E$137.P$2 60.96,107.44 81.28,107.44 | 81.28,107.44 E$123.P$13 | 98.55,77.72 E$140.P$1 104.39,65.28 E$162.P$2
S$186
  Bottom 0.61: E$138.P$1 E$128.P$1
S$187
  Bottom 0.61: E$138.P$2 101.85,110.24 109.22,110.24 E$127.P$1
S$188
  Bottom 0.61: E$129.P$1 E$138.P$4
S$189
  Bottom 0.61: E$138.P$3 99.31,110.24 90.42,110.24 E$130.P$1
S$190
  Bottom 0.61: E$139.P$1 E$132.P$1
S$191
  Bottom 0.61: E$139.P$4 E$134.P$1
S$192
  Bottom 0.61: E$131.P$1 87.88,110.24 78.99,110.24 E$139.P$2
S$193
  Bottom 0.61: E$139.P$3 76.45,110.24 67.56,110.24 E$133.P$1
S$194
  Bottom 0.61: E$140.P$4 E$140.P$3
S$195
  Bottom 0.61: E$141.P$2 E$144.P$1 57.4,75.95 59.94,79.76 E$146.P$2
S$196
  Bottom 0.61: E$141.P$3 53.59,75.18 57.4,80.77 E$144.P$2 57.4,85.09 62.48,85.09 E$156.P$1
S$198
  Bottom 0.61: E$141.P$6 37.59,75.18 E$145.P$1 37.59,82.3 50.8,82.3 E$142.P$12
S$199
  Bottom 0.61: 42.93,87.12 E$142.P$6 46.99,87.12 | 46.99,87.12 E$142.P$5 | 46.99,89.66 E$142.P$4 | 46.99,89.66 46.99,87.12 | 46.99,92.2 E$142.P$2 | 46.99,92.2 46.99,89.66 | E$142.P$8 46.99,94.74 | 46.99,94.74 46.99,92.2 | E$142.P$10 46.99,97.28 46.99,94.74
S$200
  Bottom 0.61: E$148.P$2 55.37,97.28 E$142.P$9
S$201
  Bottom 0.61: E$147.P$2 57.4,92.2 E$142.P$1
S$202
  Bottom 0.61: E$149.P$2 40.89,99.82 E$142.P$14
S$203
  Bottom 0.61: E$150.P$2 38.35,94.74 E$142.P$7
S$204
  Bottom 0.61: E$142.P$3 40.39,89.66 32,84.58 E$143.P$12
S$205
  Bottom 0.61: E$143.P$10 25.15,97.28 25.15,94.74 | E$143.P$8 25.15,94.74 | 25.15,92.2 E$143.P$2 | 25.15,94.74 25.15,92.2 | 25.15,89.66 E$143.P$4 | 25.15,92.2 25.15,89.66 | 25.15,87.12 E$143.P$6 | 25.15,89.66 25.15,87.12 | 25.15,87.12 E$143.P$5
S$206
  Bottom 0.61: E$143.P$9 33.27,97.28 E$152.P$2
S$207
  Bottom 0.61: E$143.P$1 35.81,92.2 E$151.P$2
S$208
  Bottom 0.61: E$143.P$14 18.03,99.82 E$154.P$2
S$209
  Bottom 0.61: E$143.P$7 15.49,94.74 E$153.P$2
S$210
  Bottom 0.61: E$143.P$3 E$155.P$2
S$211
  Bottom 0.61: E$157.P$1 E$155.P$1
S$214
  Bottom 0.61: E$158.P$1 E$148.P$1
S$215
  Bottom 0.61: E$158.P$2 49.78,110.24 57.4,110.24 E$147.P$1
S$216
  Bottom 0.61: E$149.P$1 E$158.P$4
S$217
  Bottom 0.61: E$158.P$3 47.24,110.24 38.35,110.24 E$150.P$1
S$218
  Bottom 0.61: E$159.P$1 E$152.P$1
S$219
  Bottom 0.61: E$159.P$4 E$154.P$1
S$220
  Bottom 0.61: E$151.P$1 35.81,110.24 26.92,110.24 E$159.P$2
S$221
  Bottom 0.61: E$159.P$3 24.38,110.24 15.49,110.24 E$153.P$1
S$222
  Bottom 0.61: E$160.P$4 E$160.P$3

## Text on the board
tNames: To Rotary Switches Pin 2 | To Rotary Switches Pin 4 | To Rotary Switches Pin 6 | To Rotary Switches Pin 8 | 8 | 7 | 6 | 5 | 4 | 3 | 2 | 1 | 8 | 7 | 6 | 5 | 4 | 3 | 2 | 1 | 8 | 7 | 6 | 5 | 4 | 3 | 2 | 1 | 8 | 7 | 6 | 5 | 4 | 3 | 2 | 1 | 220R | 220R | 220R | 220R | 220R | 220R | 220R | 220R | 220R | 220R | 220R | 220R | 220R | 220R | 220R | 220R | 220R | 220R | 220R | 220R | 220R | 220R | 220R | 220R | 220R | 220R | Activity | 220R | 220R | 220R | Activity | 220R | 220R | 220R | Activity | Activity | LED 4 | LED 6 | LED 8 | LED 2 | 220R | 220R | 220R | 220R | 7404 | 7404 | 7404 | 7404 | 7404 | 7404 | 7404 | 7404 | 9-15v AC/DC | 500ma | 1N4148 | 1N4148 | 1N4148 | 1N4148 | 220R | 220R | 220R | 220R | 6N138 | 6N138 | 6N138 | 6N138 | 1k | 1k | 1k | 1k | DB101 | Midi In | .1uf | Midi In | Midi In | Midi Out | Midi In | Midi Out | Midi Out | 6 | Midi Out | 2 | 2 | 4 | 4 | 6 | 8 | 8 | From Common of Rotary Switch | 22uf | From Common of Rotary Switch | 22uf | 22uf | 4 | 5 | 4 | 5 | From Common of Rotary Switch | 4 | 5 | From Common of Rotary Switch | 4 | 5 | 4 | 2 | 2 | 5 | 4 | 2 | 5 | 4 | 2 | 5 | 5 | 4 | 7805 | 2 | 4 | 5 | 4 | 2 | 4 | 5 | 2 | 5 | 2 | 4 | 5 | 22uf | From Common of Rotary Switch | 5 | 4 | 5 | 4 | From Common of Rotary Switch | 5 | 4 | From Common of Rotary Switch | 5 | 4 | From Common of Rotary Switch | Midi In | Midi Out | 1 | Midi Out | 3 | Midi Out | 5 | Midi In | Midi Out | 7 | 1 | Midi In | Midi In | 3 | 5 | 7 | 6N138 | 1k | 6N138 | 1k | 6N138 | 1k | 6N138 | 1k | 220R | 220R | 220R | 220R | 1N4148 | 1N4148 | 1N4148 | 1N4148 | 7404 | 7404 | 7404 | 7404 | 7404 | 7404 | 7404 | 7404 | 220R | 220R | 220R | 220R | Dragon's Lair | 8x8 Midi Patch Bay | Activity | Activity | Activity | Activity | LED 1` | LED 3 | LED 5 | 220R | 220R | 220R | 220R | 220R | 220R | 220R | 220R | 220R | 220R | 220R | 220R | 220R | 220R | 220R | 220R | 220R | 220R | 220R | 220R | 220R | 220R | 220R | LED 7 | 220R | 220R | 220R | 220R | 220R | 220R | 220R | 220R | 220R | 1 | 2 | 3 | 4 | 5 | 6 | 7 | 8 | 1 | 2 | 3 | 4 | 5 | 6 | 7 | 8 | 1 | 2 | 3 | 4 | 5 | 6 | 7 | 8 | 1 | 2 | 3 | 4 | 5 | 6 | 7 | 8 | To Rotary Switches Pin 1 | To Rotary Switches Pin 3 | To Rotary Switches Pin 5 | To Rotary Switches Pin 7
